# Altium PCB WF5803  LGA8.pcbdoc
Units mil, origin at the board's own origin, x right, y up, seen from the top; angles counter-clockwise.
Board outline 819.3 x 760 mil, 2 copper layers (Top Layer, Bottom Layer); 1 components, 0 nets, 8 pads, 0 vias.
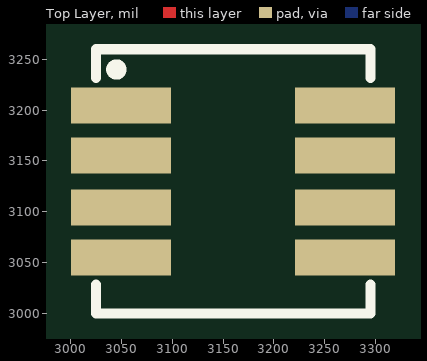
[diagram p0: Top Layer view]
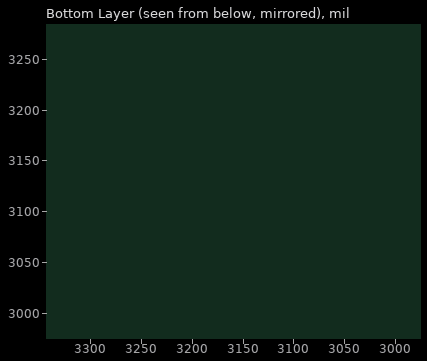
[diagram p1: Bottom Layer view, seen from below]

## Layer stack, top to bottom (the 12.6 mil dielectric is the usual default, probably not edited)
Top Layer: signal copper (thickness not stored)
Dielectric: dielectric 12.6, FR-4, Dk 4.8
Bottom Layer: signal copper (thickness not stored)

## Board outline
3569.3,2750 2750,2750 2750,3510 3569.3,3510

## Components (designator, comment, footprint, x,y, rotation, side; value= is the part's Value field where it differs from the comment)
? "LGA-8_L6.8-W6.2-P1.25-TL" LGA-8_L6.8-W6.2-P1.25-TL 3159.84,3130 r0 top

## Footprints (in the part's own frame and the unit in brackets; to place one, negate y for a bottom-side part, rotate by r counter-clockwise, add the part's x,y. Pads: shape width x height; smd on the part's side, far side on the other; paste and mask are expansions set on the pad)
LGA-8_L6.8-W6.2-P1.25-TL [mm]
  rect 2.5x0.9 smd paste+0 mask+0.05: 1(-2.8,1.9) 2(-2.8,0.65) 3(-2.8,-0.65) 4(-2.8,-1.9) 5(2.8,-1.9) 6(2.8,-0.65) 7(2.8,0.65) 8(2.8,1.9)
  silkscreen extent -3.43,-3.3 3.43,3.3

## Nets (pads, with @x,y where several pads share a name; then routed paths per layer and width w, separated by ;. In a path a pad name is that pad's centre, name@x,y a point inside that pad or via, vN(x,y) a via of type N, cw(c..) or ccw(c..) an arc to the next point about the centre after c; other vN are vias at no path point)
pads on no net: ?.1 ?.2 ?.3 ?.4 ?.5 ?.6 ?.7 ?.8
